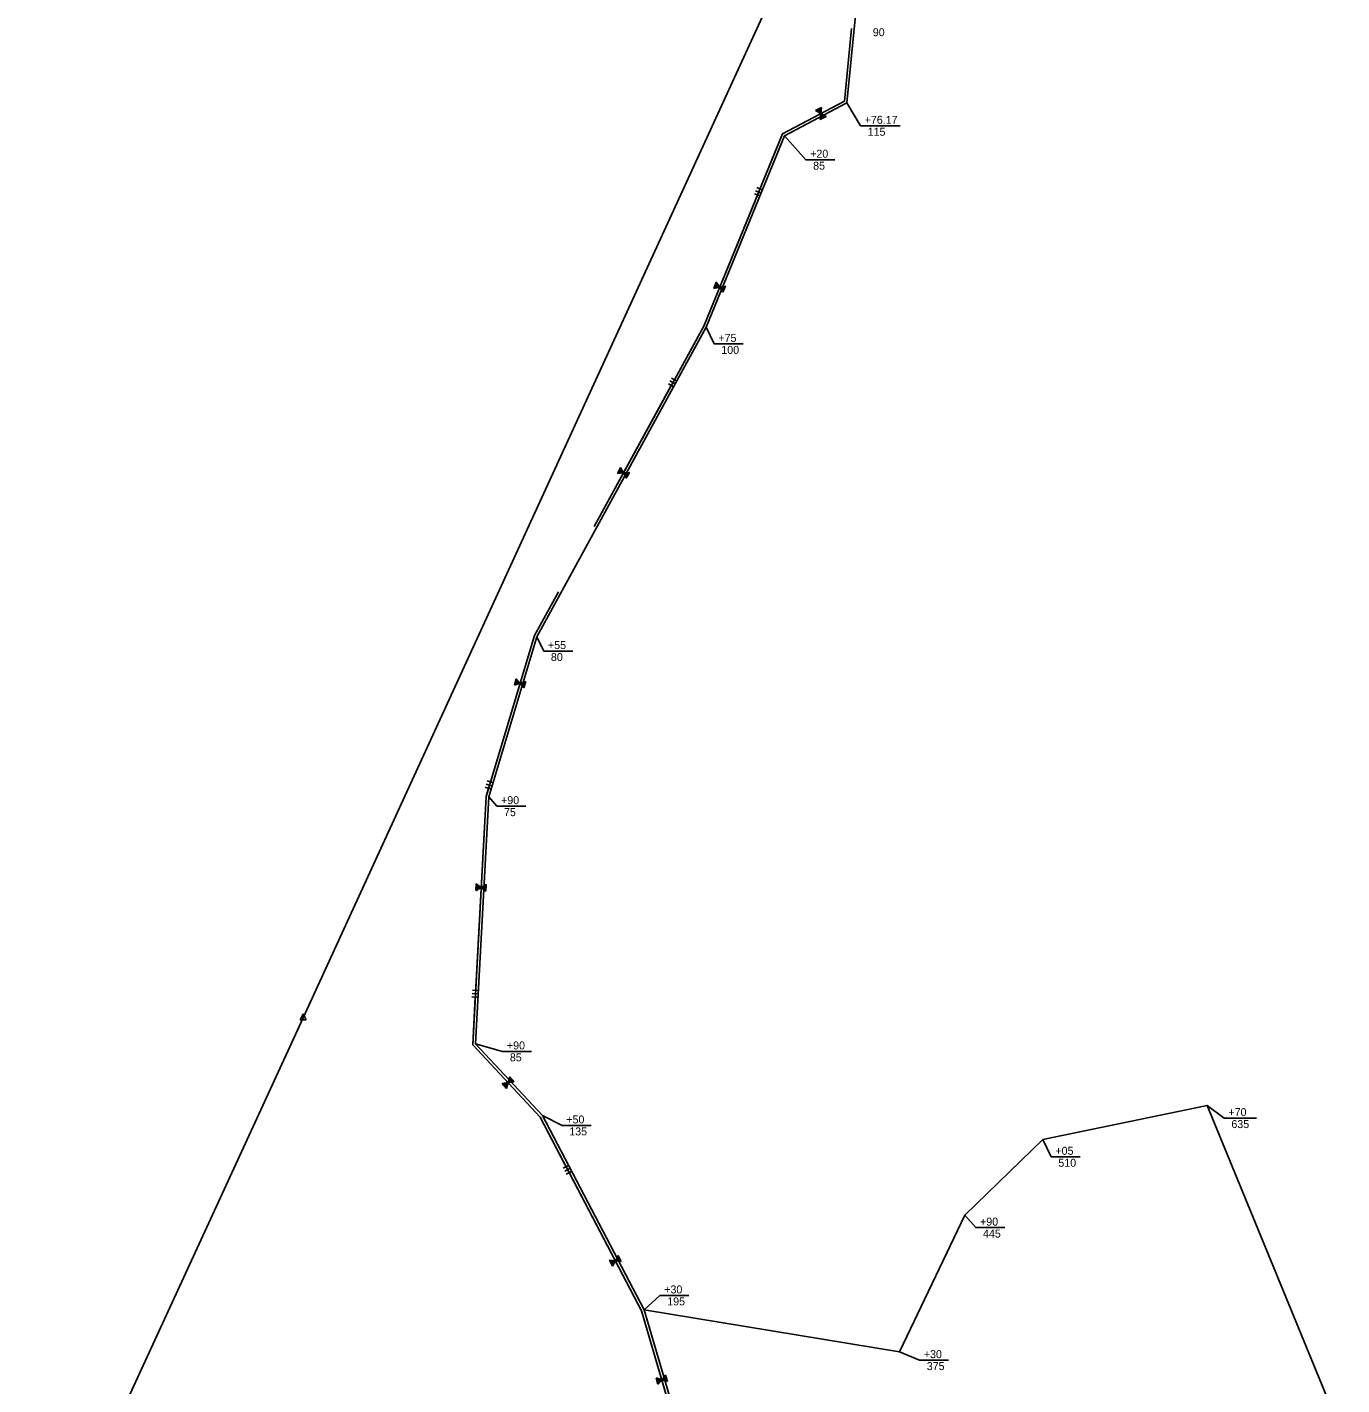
# Model space of a CAD drawing. Extents: x 979729 to 993523, y 1834148 to 1845433.
# Drawn here: x 980333 to 981322, y 1839343 to 1840365 of the extents above; entities that cross this region are included whole.
import ezdxf

# ---------------------------------------------------------------- set-up
doc = ezdxf.new("R2010")
doc.units = 0
for name, color, linetype in [('42', 7, 'Continuous'), ('51', 7, 'Continuous'), ('53', 7, 'Continuous'), ('R_Draft', 7, 'Continuous'), ('S_EXIST_ROW', 7, 'Continuous')]:
    doc.layers.add(name, color=color, linetype=linetype)

msp = doc.modelspace()

# ---------------------------------------------------------------- linework, layer by layer
at = {"layer": '42'}
for p, q in [((980953.4, 1840364), (980948.1, 1840309.3)), ((980948.1, 1840309.3), (980901.4, 1840284.7)), ((980930.4, 1840300), (980926.4, 1840302.1)), ((980930.4, 1840300.1), (980926.5, 1840302.2)), ((980930.4, 1840300.3), (980926.8, 1840302.3)), ((980930.4, 1840300.6), (980927.1, 1840302.4)), ((980930.5, 1840300.9), (980927.3, 1840302.6)), ((980930.5, 1840301.1), (980927.6, 1840302.7)), ((980930.5, 1840301.4), (980927.8, 1840302.9)), ((980930.6, 1840301.7), (980928.1, 1840303)), ((980930.5, 1840302), (980928.4, 1840303.1)), ((980930.6, 1840302.2), (980928.6, 1840303.3)), ((980930.6, 1840302.5), (980929.1, 1840303.3)), ((980930.7, 1840302.7), (980929.2, 1840303.6)), ((980930.7, 1840303), (980929.4, 1840303.7)), ((980930.7, 1840303.3), (980929.7, 1840303.8)), ((980930.4, 1840300), (980929.9, 1840295.5)), ((980930.7, 1840303.6), (980930, 1840304)), ((980930.5, 1840299.9), (980930, 1840295.5)), ((980930.8, 1840303.8), (980930.2, 1840304.1)), ((980930.7, 1840299.7), (980930.3, 1840295.7)), ((980930.9, 1840304.4), (980930.4, 1840300)), ((980934.4, 1840297.8), (980930.4, 1840300)), ((980930.8, 1840304.1), (980930.5, 1840304.3)), ((980930.9, 1840299.6), (980930.6, 1840295.8)), ((980930.8, 1840304.4), (980930.8, 1840304.4)), ((980931.2, 1840299.5), (980930.8, 1840295.9)), ((980931.4, 1840299.4), (980931.1, 1840296.1)), ((980931.7, 1840299.2), (980931.3, 1840296.2)), ((980931.9, 1840299.1), (980931.6, 1840296.4)), ((980932.1, 1840298.9), (980931.9, 1840296.5)), ((980932.4, 1840298.8), (980932.1, 1840296.6)), ((980932.6, 1840298.6), (980932.4, 1840296.9)), ((980932.9, 1840298.6), (980932.7, 1840296.9)), ((980933.1, 1840298.5), (980932.9, 1840297.1)), ((980933.3, 1840298.3), (980933.2, 1840297.2)), ((980933.6, 1840298.2), (980933.5, 1840297.3)), ((980933.8, 1840298.1), (980933.7, 1840297.5)), ((980934, 1840297.9), (980934, 1840297.6)), ((980934.3, 1840297.8), (980934.3, 1840297.8)), ((980901.4, 1840284.7), (980842.2, 1840140)), ((980884.9, 1840237.7), (980880.3, 1840239.6)), ((980885.8, 1840240), (980881.2, 1840241.9)), ((980886.8, 1840242.3), (980882.2, 1840244.2)), ((980854.1, 1840169.3), (980849.8, 1840168.4)), ((980854.2, 1840169.2), (980849.8, 1840168.3)), ((980853.9, 1840169.5), (980849.9, 1840168.7)), ((980853.8, 1840169.7), (980850, 1840169)), ((980853.6, 1840170), (980850.1, 1840169.3)), ((980853.5, 1840170.2), (980850.2, 1840169.5)), ((980853.3, 1840170.4), (980850.4, 1840169.8)), ((980853.2, 1840170.6), (980850.5, 1840170.1)), ((980853, 1840170.9), (980850.6, 1840170.4)), ((980852.9, 1840171.1), (980850.7, 1840170.7)), ((980852.6, 1840171.5), (980850.9, 1840171.2)), ((980852.4, 1840171.8), (980851, 1840171.5)), ((980852.7, 1840171.3), (980851, 1840171)), ((980852.3, 1840172), (980851.2, 1840171.8)), ((980852.1, 1840172.2), (980851.3, 1840172)), ((980852, 1840172.4), (980851.4, 1840172.3)), ((980851.8, 1840172.7), (980851.5, 1840172.6)), ((980851.6, 1840173), (980854.2, 1840169.2)), ((980851.7, 1840172.9), (980851.6, 1840172.9)), ((980858.6, 1840170.1), (980854.2, 1840169.2)), ((980854.2, 1840169.2), (980856.7, 1840165.5)), ((980854.3, 1840169.2), (980856.7, 1840165.6)), ((980854.6, 1840169.2), (980856.8, 1840165.9)), ((980854.8, 1840169.3), (980857, 1840166.1)), ((980855.1, 1840169.4), (980857.1, 1840166.4)), ((980855.3, 1840169.4), (980857.2, 1840166.7)), ((980855.6, 1840169.5), (980857.3, 1840167)), ((980855.9, 1840169.6), (980857.4, 1840167.3)), ((980856.2, 1840169.6), (980857.5, 1840167.5)), ((980856.4, 1840169.6), (980857.6, 1840167.8)), ((980856.7, 1840169.6), (980857.7, 1840168.2)), ((980856.9, 1840169.8), (980857.9, 1840168.4)), ((980857.2, 1840169.8), (980858, 1840168.6)), ((980857.5, 1840169.9), (980858.1, 1840168.9)), ((980857.7, 1840169.9), (980858.2, 1840169.2)), ((980858, 1840170), (980858.3, 1840169.5)), ((980858.3, 1840170), (980858.4, 1840169.8)), ((980858.5, 1840170.1), (980858.6, 1840170)), ((980842.2, 1840140), (980759.7, 1839989.1)), ((980820, 1840094.1), (980815.6, 1840096.5)), ((980821.2, 1840096.3), (980816.8, 1840098.7)), ((980822.4, 1840098.5), (980818, 1840100.9)), ((980781.3, 1840030.3), (980777.8, 1840030)), ((980781.2, 1840030.6), (980777.9, 1840030.3)), ((980781.1, 1840030.8), (980778.1, 1840030.5)), ((980781, 1840031), (980778.2, 1840030.8)), ((980780.8, 1840031.3), (980778.4, 1840031.1)), ((980780.7, 1840031.5), (980778.5, 1840031.3)), ((980780.5, 1840032), (980778.8, 1840031.8)), ((980780.5, 1840031.7), (980778.8, 1840031.6)), ((980780.4, 1840032.2), (980778.9, 1840032.1)), ((980780.2, 1840032.5), (980779.1, 1840032.4)), ((980780.1, 1840032.7), (980779.2, 1840032.6)), ((980780, 1840033), (980779.4, 1840032.9)), ((980779.8, 1840033.2), (980779.5, 1840033.2)), ((980779.7, 1840033.5), (980781.8, 1840029.5)), ((980779.7, 1840033.4), (980779.7, 1840033.4)), ((980781.8, 1840029.5), (980777.3, 1840029.1)), ((980781.7, 1840029.6), (980777.4, 1840029.2)), ((980781.6, 1840029.8), (980777.5, 1840029.5)), ((980781.5, 1840030.1), (980777.6, 1840029.7)), ((980786.3, 1840029.9), (980781.8, 1840029.5)), ((980781.8, 1840029.5), (980783.9, 1840025.5)), ((980781.9, 1840029.5), (980783.9, 1840025.6)), ((980782.2, 1840029.5), (980784.1, 1840025.9)), ((980782.4, 1840029.6), (980784.2, 1840026.1)), ((980782.7, 1840029.6), (980784.4, 1840026.4)), ((980783, 1840029.6), (980784.5, 1840026.7)), ((980783.3, 1840029.6), (980784.7, 1840026.9)), ((980783.5, 1840029.7), (980784.8, 1840027.2)), ((980783.8, 1840029.6), (980784.9, 1840027.5)), ((980784.1, 1840029.7), (980785.1, 1840027.7)), ((980784.4, 1840029.6), (980785.2, 1840028.1)), ((980784.6, 1840029.7), (980785.4, 1840028.2)), ((980784.9, 1840029.8), (980785.5, 1840028.5)), ((980785.1, 1840029.8), (980785.7, 1840028.8)), ((980785.4, 1840029.8), (980785.8, 1840029)), ((980785.7, 1840029.8), (980786, 1840029.3)), ((980786, 1840029.8), (980786.1, 1840029.6)), ((980786.2, 1840029.9), (980786.2, 1840029.8)), ((980732.9, 1839940.1), (980714.9, 1839907.1)), ((980714.9, 1839907.1), (980678.4, 1839786.2)), ((980704, 1839871.3), (980699.7, 1839869.9)), ((980704, 1839871.3), (980699.8, 1839870)), ((980703.6, 1839871.7), (980699.9, 1839870.6)), ((980703.8, 1839871.5), (980699.9, 1839870.3)), ((980703.4, 1839871.9), (980700, 1839870.9)), ((980703.3, 1839872.2), (980700.1, 1839871.2)), ((980703.1, 1839872.3), (980700.2, 1839871.5)), ((980702.9, 1839872.6), (980700.3, 1839871.8)), ((980702.7, 1839872.8), (980700.4, 1839872.1)), ((980702.6, 1839873), (980700.5, 1839872.3)), ((980702.2, 1839873.4), (980700.6, 1839872.9)), ((980702.1, 1839873.6), (980700.7, 1839873.2)), ((980702.3, 1839873.2), (980700.7, 1839872.7)), ((980701.9, 1839873.8), (980700.8, 1839873.5)), ((980701.7, 1839874), (980700.9, 1839873.8)), ((980701.6, 1839874.2), (980701, 1839874.1)), ((980701.4, 1839874.4), (980701.1, 1839874.4)), ((980701.2, 1839874.7), (980701.2, 1839874.6)), ((980701.2, 1839874.7), (980704, 1839871.3)), ((980708.4, 1839872.6), (980704, 1839871.3)), ((980704, 1839871.3), (980706.9, 1839867.8)), ((980704.1, 1839871.3), (980706.9, 1839867.9)), ((980704.4, 1839871.3), (980707, 1839868.2)), ((980704.7, 1839871.4), (980707.1, 1839868.4)), ((980704.9, 1839871.5), (980707.2, 1839868.7)), ((980705.2, 1839871.6), (980707.3, 1839869)), ((980705.5, 1839871.6), (980707.4, 1839869.3)), ((980705.7, 1839871.7), (980707.5, 1839869.6)), ((980706, 1839871.8), (980707.6, 1839869.9)), ((980706.2, 1839871.9), (980707.6, 1839870.2)), ((980706.5, 1839871.9), (980707.6, 1839870.6)), ((980706.7, 1839872.1), (980707.8, 1839870.8)), ((980707, 1839872.1), (980707.9, 1839871)), ((980707.3, 1839872.2), (980708, 1839871.3)), ((980707.5, 1839872.3), (980708.1, 1839871.6)), ((980707.8, 1839872.4), (980708.2, 1839871.9)), ((980708, 1839872.4), (980708.2, 1839872.2)), ((980708.3, 1839872.5), (980708.3, 1839872.5)), ((980683.3, 1839793.9), (980678.6, 1839795.4)), ((980684.1, 1839796.3), (980679.3, 1839797.8)), ((980678.4, 1839786.2), (980668.4, 1839599.3)), ((980682.6, 1839791.5), (980677.8, 1839793)), ((980674.7, 1839717.6), (980670.8, 1839715.3)), ((980673.5, 1839718.5), (980670.9, 1839716.9)), ((980673.8, 1839718.3), (980670.9, 1839716.6)), ((980674, 1839718.2), (980670.9, 1839716.3)), ((980674.2, 1839718), (980670.9, 1839716)), ((980674.4, 1839717.8), (980670.9, 1839715.7)), ((980674.6, 1839717.7), (980670.9, 1839715.4)), ((980672, 1839719.6), (980671, 1839719)), ((980672.3, 1839719.5), (980671, 1839718.7)), ((980672.5, 1839719.3), (980671, 1839718.4)), ((980672.9, 1839719), (980671, 1839717.8)), ((980673.1, 1839718.8), (980671, 1839717.5)), ((980673.3, 1839718.7), (980671, 1839717.2)), ((980671.2, 1839720.3), (980671.1, 1839720.2)), ((980671.1, 1839720.3), (980674.7, 1839717.6)), ((980671.4, 1839720.1), (980671.1, 1839719.9)), ((980671.6, 1839719.9), (980671.1, 1839719.6)), ((980671.8, 1839719.8), (980671.1, 1839719.3)), ((980672.6, 1839719.1), (980671.1, 1839718.2)), ((980678.6, 1839719.9), (980674.7, 1839717.6)), ((980674.7, 1839717.6), (980678.3, 1839714.9)), ((980674.8, 1839717.7), (980678.3, 1839715)), ((980675.1, 1839717.8), (980678.4, 1839715.3)), ((980675.3, 1839717.9), (980678.4, 1839715.6)), ((980675.5, 1839718.1), (980678.4, 1839715.9)), ((980675.8, 1839718.2), (980678.4, 1839716.2)), ((980676, 1839718.3), (980678.4, 1839716.5)), ((980676.2, 1839718.5), (980678.4, 1839716.8)), ((980676.5, 1839718.6), (980678.5, 1839717.1)), ((980676.7, 1839718.8), (980678.5, 1839717.4)), ((980677, 1839718.9), (980678.4, 1839717.8)), ((980677.2, 1839719), (980678.5, 1839718)), ((980677.4, 1839719.2), (980678.5, 1839718.3)), ((980677.6, 1839719.3), (980678.5, 1839718.6)), ((980677.9, 1839719.5), (980678.6, 1839718.9)), ((980678.1, 1839719.6), (980678.6, 1839719.2)), ((980678.3, 1839719.7), (980678.6, 1839719.5)), ((980678.5, 1839719.9), (980678.6, 1839719.8)), ((980672.8, 1839635.1), (980667.8, 1839635.4)), ((980673, 1839637.6), (980668, 1839637.9)), ((980673.1, 1839640.1), (980668.1, 1839640.4)), ((980668.4, 1839599.3), (980719.1, 1839544.9)), ((980690.5, 1839570.1), (980695, 1839570.8)), ((980694.1, 1839570.6), (980693.3, 1839567.1)), ((980694.4, 1839570.7), (980693.5, 1839566.9)), ((980694.6, 1839570.7), (980693.7, 1839566.7)), ((980694.9, 1839570.8), (980693.9, 1839566.5)), ((980695, 1839570.8), (980693.9, 1839566.4)), ((980696, 1839575.2), (980695, 1839570.8)), ((980695, 1839570.9), (980699.4, 1839571.6)), ((980695, 1839570.8), (980699.4, 1839571.5)), ((980695.1, 1839571.4), (980698.9, 1839572)), ((980695.1, 1839571.1), (980699.2, 1839571.8)), ((980695.2, 1839571.7), (980698.7, 1839572.2)), ((980695.3, 1839571.9), (980698.5, 1839572.5)), ((980695.4, 1839572.5), (980698.1, 1839572.9)), ((980695.4, 1839572.2), (980698.3, 1839572.7)), ((980695.5, 1839573), (980697.7, 1839573.3)), ((980695.5, 1839572.7), (980697.9, 1839573.1)), ((980695.6, 1839573.5), (980697.3, 1839573.8)), ((980695.7, 1839573.8), (980697.1, 1839574)), ((980695.7, 1839573.3), (980697.3, 1839573.5)), ((980695.8, 1839574.3), (980696.7, 1839574.4)), ((980695.8, 1839574), (980696.9, 1839574.2)), ((980695.9, 1839574.6), (980696.5, 1839574.7)), ((980696, 1839575.1), (980696.1, 1839575.1)), ((980696, 1839574.8), (980696.3, 1839574.9)), ((980690.6, 1839570), (980690.6, 1839570)), ((980690.9, 1839570.1), (980690.8, 1839569.8)), ((980691.1, 1839570.1), (980691, 1839569.5)), ((980691.4, 1839570.2), (980691.2, 1839569.3)), ((980691.7, 1839570.2), (980691.4, 1839569.1)), ((980692, 1839570.3), (980691.6, 1839568.9)), ((980692.2, 1839570.3), (980691.8, 1839568.7)), ((980692.5, 1839570.3), (980692.1, 1839568.6)), ((980692.7, 1839570.4), (980692.2, 1839568.2)), ((980693, 1839570.4), (980692.4, 1839568)), ((980693.3, 1839570.5), (980692.6, 1839567.8)), ((980693.5, 1839570.5), (980692.9, 1839567.6)), ((980693.8, 1839570.6), (980693.1, 1839567.4)), ((980719.1, 1839544.9), (980795.4, 1839399)), ((980740.9, 1839508.8), (980736.4, 1839506.4)), ((980742, 1839506.5), (980737.6, 1839504.2)), ((980743.2, 1839504.3), (980738.7, 1839502)), ((980777.9, 1839440.7), (980775.7, 1839436.7)), ((980776.5, 1839438), (980779.5, 1839437.6)), ((980776.6, 1839438.2), (980779.3, 1839437.9)), ((980776.7, 1839438.4), (980779.2, 1839438.2)), ((980776.8, 1839438.7), (980779, 1839438.4)), ((980777, 1839438.9), (980778.7, 1839438.7)), ((980777.1, 1839439.2), (980778.8, 1839439)), ((980777.2, 1839439.4), (980778.6, 1839439.2)), ((980777.3, 1839439.6), (980778.5, 1839439.5)), ((980777.5, 1839439.9), (980778.3, 1839439.8)), ((980777.6, 1839440.1), (980778.2, 1839440)), ((980777.7, 1839440.3), (980778.1, 1839440.3)), ((980777.9, 1839440.6), (980777.9, 1839440.6)), ((980771.2, 1839437.2), (980775.7, 1839436.7)), ((980771.3, 1839437.2), (980771.3, 1839437.1)), ((980771.6, 1839437.1), (980771.4, 1839436.8)), ((980771.8, 1839437.1), (980771.6, 1839436.6)), ((980772.1, 1839437.1), (980771.7, 1839436.3)), ((980772.4, 1839437), (980771.8, 1839436)), ((980772.7, 1839437), (980772, 1839435.8)), ((980772.9, 1839437), (980772.1, 1839435.5)), ((980773.2, 1839436.9), (980772.3, 1839435.4)), ((980773.4, 1839436.9), (980772.4, 1839435)), ((980773.7, 1839436.9), (980772.5, 1839434.7)), ((980774, 1839436.9), (980772.7, 1839434.4)), ((980774.2, 1839436.8), (980772.8, 1839434.2)), ((980774.5, 1839436.8), (980772.9, 1839433.9)), ((980774.8, 1839436.8), (980773.1, 1839433.6)), ((980775.1, 1839436.8), (980773.2, 1839433.4)), ((980775.3, 1839436.7), (980773.4, 1839433.1)), ((980775.6, 1839436.7), (980773.5, 1839432.8)), ((980775.7, 1839436.7), (980773.5, 1839432.8)), ((980775.7, 1839436.7), (980780.2, 1839436.2)), ((980775.8, 1839436.8), (980780.1, 1839436.3)), ((980776, 1839437.3), (980779.9, 1839436.9)), ((980776, 1839437), (980780, 1839436.6)), ((980776.2, 1839437.5), (980779.7, 1839437.1)), ((980776.3, 1839437.7), (980779.6, 1839437.4)), ((980795.4, 1839399), (980846.6, 1839224.9)), ((980806.3, 1839348.7), (980810.6, 1839347.3)), ((980806.4, 1839348.6), (980806.3, 1839348.6)), ((980806.6, 1839348.5), (980806.4, 1839348.3)), ((980806.9, 1839348.5), (980806.5, 1839348)), ((980807.1, 1839348.4), (980806.6, 1839347.7)), ((980807.4, 1839348.3), (980806.7, 1839347.4)), ((980807.7, 1839348.2), (980806.8, 1839347.1)), ((980807.9, 1839348.1), (980806.8, 1839346.8)), ((980808.1, 1839348), (980807, 1839346.7)), ((980808.4, 1839347.9), (980807, 1839346.3)), ((980808.7, 1839347.9), (980807.1, 1839346)), ((980809, 1839347.8), (980807.2, 1839345.7)), ((980809.2, 1839347.7), (980807.3, 1839345.4)), ((980809.5, 1839347.6), (980807.4, 1839345.1)), ((980809.7, 1839347.6), (980807.4, 1839344.8)), ((980810, 1839347.5), (980807.5, 1839344.5)), ((980810.2, 1839347.4), (980807.6, 1839344.2)), ((980810.5, 1839347.3), (980807.7, 1839344)), ((980810.6, 1839347.3), (980807.7, 1839343.9)), ((980813.5, 1839350.8), (980810.6, 1839347.3)), ((980810.6, 1839347.3), (980814.9, 1839346)), ((980810.7, 1839347.4), (980814.9, 1839346.1)), ((980810.9, 1839347.6), (980814.8, 1839346.4)), ((980811, 1839347.8), (980814.7, 1839346.6)), ((980811.2, 1839348), (980814.6, 1839346.9)), ((980811.4, 1839348.2), (980814.5, 1839347.2)), ((980811.6, 1839348.4), (980814.5, 1839347.5)), ((980811.7, 1839348.6), (980814.4, 1839347.8)), ((980812, 1839348.8), (980814.3, 1839348.1)), ((980812.1, 1839349), (980814.2, 1839348.4)), ((980812.3, 1839349.2), (980814, 1839348.7)), ((980812.4, 1839349.5), (980814, 1839348.9)), ((980812.6, 1839349.7), (980814, 1839349.2)), ((980812.8, 1839349.9), (980813.9, 1839349.5)), ((980813, 1839350.1), (980813.8, 1839349.8)), ((980813.1, 1839350.3), (980813.7, 1839350.1)), ((980813.3, 1839350.5), (980813.6, 1839350.4)), ((980813.5, 1839350.7), (980813.5, 1839350.7))]:
    msp.add_line(p, q, dxfattribs=at)
for points in [[(980953.4, 1840364), (980948.1, 1840309.3), (980901.4, 1840284.7), (980885.4, 1840245.6)], [(980930.9, 1840304.4), (980926.4, 1840302.1)], [(980934.4, 1840297.8), (980929.9, 1840295.5)], [(980882.6, 1840238.6), (980842.2, 1840140), (980821.4, 1840101.9)], [(980851.6, 1840173), (980849.8, 1840168.3)], [(980858.6, 1840170.1), (980856.7, 1840165.5)], [(980817.8, 1840095.3), (980759.7, 1839989.1)], [(980779.7, 1840033.5), (980777.3, 1840029.1)], [(980786.3, 1840029.9), (980783.9, 1840025.5)], [(980732.9, 1839940.1), (980714.9, 1839907.1), (980682.4, 1839799.4)], [(980701.2, 1839874.7), (980699.7, 1839869.9)], [(980708.4, 1839872.6), (980706.9, 1839867.8)], [(980680.2, 1839792.3), (980678.4, 1839786.2), (980670.7, 1839642.7)], [(980671.1, 1839720.3), (980670.8, 1839715.3)], [(980678.6, 1839719.9), (980678.3, 1839714.9)], [(980670.3, 1839635.3), (980668.4, 1839599.3), (980719.1, 1839544.9), (980737.5, 1839509.8)], [(980696, 1839575.2), (980699.4, 1839571.5)], [(980690.5, 1839570.1), (980693.9, 1839566.4)], [(980741, 1839503.2), (980795.4, 1839399)], [(980777.9, 1839440.7), (980780.2, 1839436.2)], [(980771.2, 1839437.2), (980773.5, 1839432.8)], [(980795.4, 1839399), (980846.6, 1839224.9), (980843.6, 1839216.9)], [(980806.3, 1839348.7), (980807.7, 1839343.9)], [(980813.5, 1839350.8), (980814.9, 1839346)]]:
    msp.add_lwpolyline(points, dxfattribs=at)
at = {"layer": '51'}
for points in [[(980949.9, 1840308), (980956.3, 1840373.8), (981026, 1840495.3), (981108.7, 1840491.3), (981205.8, 1840536.2), (981170.4, 1840619.1)], [(981283.2, 1838700.8), (981086.4, 1838800.5), (980950.4, 1838993.5), (980807.1, 1839110.9), (980848.7, 1839224.9), (980797.3, 1839399.8), (980720.8, 1839546.1), (980670.4, 1839600), (980680.4, 1839785.8), (980716.7, 1839906.3), (980844, 1840139.1), (980903, 1840283.2), (980949.9, 1840308)]]:
    msp.add_lwpolyline(points, dxfattribs=at)
at = {"layer": '53'}
for p, q in [((981097.3, 1839527.9), (981220.9, 1839553.5)), ((981220.9, 1839553.5), (981322.3, 1839307.3)), ((981038.6, 1839471), (981097.3, 1839527.9)), ((980989.6, 1839368.3), (981038.6, 1839471)), ((980797.3, 1839399.8), (980989.6, 1839368.3))]:
    msp.add_line(p, q, dxfattribs=at)
at = {"layer": 'R_Draft'}
for p, q in [((980966.1, 1840290.7), (980990, 1840290.7)), ((980925.1, 1840265.2), (980940.9, 1840265.2)), ((980856.1, 1840126.6), (980871.9, 1840126.6)), ((980727.8, 1839895.5), (980743.6, 1839895.5)), ((980692.6, 1839778.8), (980708.4, 1839778.8)), ((980696.9, 1839594.3), (980712.7, 1839594.3)), ((981239.8, 1839544.1), (981258.1, 1839544.1)), ((980741.6, 1839538.6), (980757.4, 1839538.6)), ((981109.7, 1839515), (981125.5, 1839515)), ((981052.9, 1839461.7), (981068.7, 1839461.7)), ((980815.3, 1839410.7), (980831.1, 1839410.7)), ((981010.6, 1839362), (981026.4, 1839362))]:
    msp.add_line(p, q, dxfattribs=at)
for points in [[(980949.9, 1840308), (980960.1, 1840290.7), (980966.1, 1840290.7)], [(980903, 1840283.2), (980919.1, 1840265.2), (980925.1, 1840265.2)], [(980844, 1840139.1), (980850.1, 1840126.6), (980856.1, 1840126.6)], [(980716.7, 1839906.3), (980721.8, 1839895.5), (980727.8, 1839895.5)], [(980680.4, 1839785.8), (980686.6, 1839778.8), (980692.6, 1839778.8)], [(980670.4, 1839600), (980690.9, 1839594.3), (980696.9, 1839594.3)], [(981220.9, 1839553.5), (981233.8, 1839544.1), (981239.8, 1839544.1)], [(980720.8, 1839546.1), (980735.6, 1839538.6), (980741.6, 1839538.6)], [(981097.3, 1839527.9), (981103.7, 1839515), (981109.7, 1839515)], [(981038.6, 1839471), (981046.9, 1839461.7), (981052.9, 1839461.7)], [(980797.3, 1839399.8), (980809.3, 1839410.7), (980815.3, 1839410.7)], [(980989.6, 1839368.3), (981004.6, 1839362), (981010.6, 1839362)]]:
    msp.add_lwpolyline(points, dxfattribs=at)
at = {"layer": 'S_EXIST_ROW'}
for p, q in [((980540.8, 1839619.6), (980913.4, 1840432)), ((980540.8, 1839622.6), (980538.5, 1839618.1)), ((980540.8, 1839622.6), (980543, 1839618.1)), ((980333.1, 1839168.5), (980540.8, 1839619.6)), ((980538.5, 1839618.1), (980543, 1839618.1)), ((980540.8, 1839619.6), (980540.8, 1839619.6))]:
    msp.add_line(p, q, dxfattribs=at)
for radius in [0.0768, 0.0384]:
    msp.add_circle((980540.8, 1839619.6), radius, dxfattribs=at)

# ---------------------------------------------------------------- texts
at = {"layer": 'R_Draft'}
for s, p in [(' 90', (980967.2, 1840358.1)), ('+76.17', (980963.3, 1840292.2)), (' 115', (980963.3, 1840283.2)), ('+20', (980922.3, 1840266.7)), (' 85', (980922.3, 1840257.7)), ('+75', (980853.2, 1840128.1)), (' 100', (980853.2, 1840119.1)), ('+55', (980725, 1839897)), (' 80', (980725, 1839888)), ('+90', (980689.7, 1839780.3)), (' 75', (980689.7, 1839771.3)), ('+90', (980694.1, 1839595.8)), (' 85', (980694.1, 1839586.8)), ('+70', (981237, 1839545.6)), ('+50', (980738.8, 1839540.1)), (' 635', (981237, 1839536.6)), (' 135', (980738.8, 1839531.1)), ('+05', (981106.8, 1839516.5)), (' 510', (981106.8, 1839507.5)), ('+90', (981050.1, 1839463.2)), (' 445', (981050.1, 1839454.2)), ('+30', (980812.5, 1839412.2)), (' 195', (980812.5, 1839403.2)), ('+30', (981007.8, 1839363.5)), (' 375', (981007.8, 1839354.5))]:
    msp.add_text(s, height=6, rotation=360, dxfattribs=at).set_placement(p)

doc.saveas('drawing.dxf')
